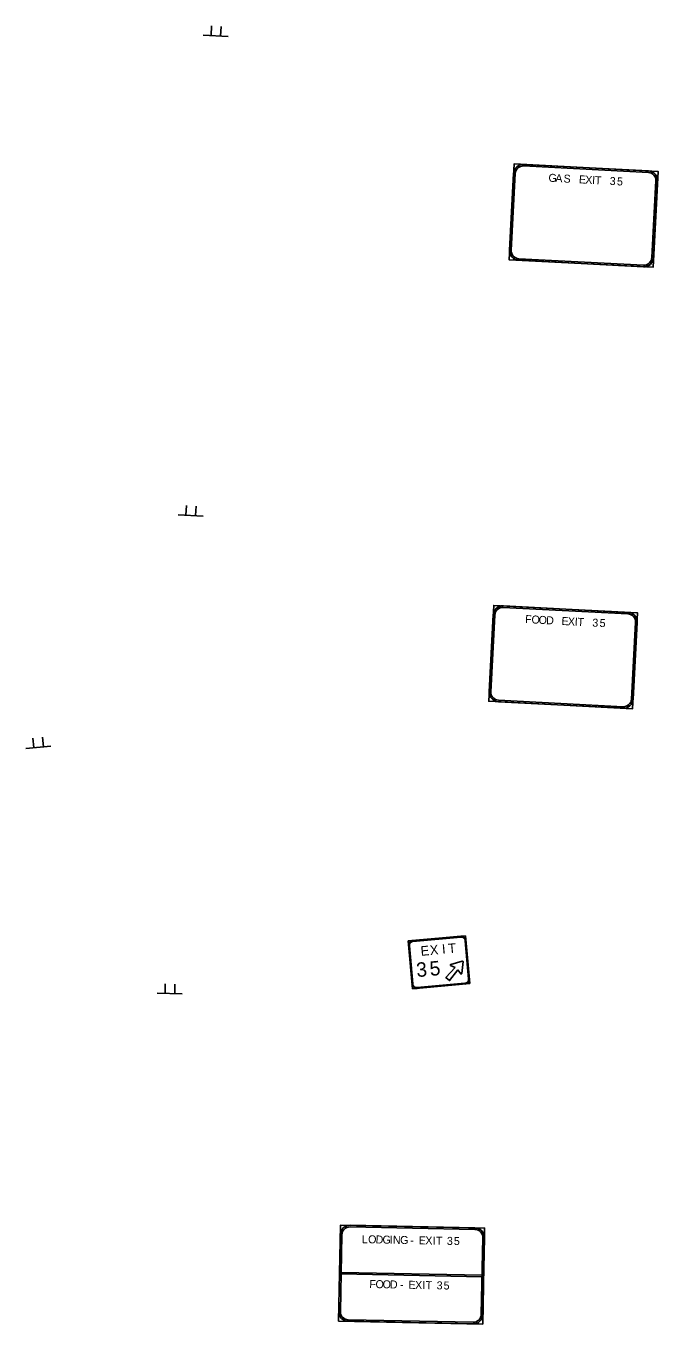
# Model space of a CAD drawing. Extents: x 1581789 to 1622364, y 1043167 to 1103486.
# Drawn here: x 1612565 to 1612828, y 1089298 to 1089839 of the extents above; entities that cross this region are included whole.
import ezdxf

# ---------------------------------------------------------------- set-up
doc = ezdxf.new("R2010")
doc.units = 0
doc.layers.add('RD_PD_PaveDit', color=7, linetype='Continuous')

msp = doc.modelspace()

# ---------------------------------------------------------------- linework, layer by layer
at = {"layer": 'RD_PD_PaveDit'}
for p, q in [((1612649.09, 1089834.18), (1612638.67, 1089834.73)), ((1612641.95, 1089834.56), (1612642.16, 1089838.54)), ((1612645.96, 1089834.35), (1612646.17, 1089838.33)), ((1612638.62, 1089634.46), (1612628.21, 1089635)), ((1612631.49, 1089634.83), (1612631.7, 1089638.82)), ((1612635.5, 1089634.62), (1612635.71, 1089638.61)), ((1612572.17, 1089538.37), (1612571.82, 1089542.34)), ((1612575.29, 1089538.65), (1612564.9, 1089537.71)), ((1612568.17, 1089538.01), (1612567.82, 1089541.99)), ((1612747.92, 1089459.65), (1612724.02, 1089457.51)), ((1612724.02, 1089457.51), (1612725.81, 1089437.59)), ((1612749.71, 1089439.74), (1612747.92, 1089459.65)), ((1612724.74, 1089449.54), (1612724.74, 1089449.54)), ((1612622.81, 1089435.64), (1612622.89, 1089439.63)), ((1612626.82, 1089435.56), (1612626.9, 1089439.55)), ((1612725.81, 1089437.59), (1612749.71, 1089439.74)), ((1612629.95, 1089435.5), (1612619.52, 1089435.71)), ((1612725.81, 1089437.59), (1612725.81, 1089437.59)), ((1612739.75, 1089438.84), (1612739.75, 1089438.84)), ((1612754.79, 1089317.66), (1612696.13, 1089318.84)), ((1612696.14, 1089319.51), (1612754.8, 1089318.32)), ((1612696.14, 1089319.51), (1612696.14, 1089319.51))]:
    msp.add_line(p, q, dxfattribs=at)
for points in [[(1612766.06, 1089741.17), (1612825.98, 1089738.04), (1612828.07, 1089777.98), (1612768.15, 1089781.12), (1612766.06, 1089741.17), (1612766.06, 1089741.17)], [(1612824.04, 1089777.52), (1612772.11, 1089780.24)], [(1612772.15, 1089780.91), (1612824.08, 1089778.19)], [(1612766.27, 1089745.17), (1612767.95, 1089777.13)], [(1612768.61, 1089777.09), (1612766.94, 1089745.13)], [(1612825.52, 1089742.07), (1612827.2, 1089774.02)], [(1612827.86, 1089773.99), (1612826.19, 1089742.03)], [(1612821.99, 1089738.25), (1612770.06, 1089740.97)], [(1612770.09, 1089741.63), (1612822.02, 1089738.91)], [(1612757.58, 1089557.32), (1612817.5, 1089554.18), (1612819.59, 1089594.13), (1612759.67, 1089597.27), (1612757.58, 1089557.32), (1612757.58, 1089557.32)], [(1612815.56, 1089593.67), (1612763.63, 1089596.39)], [(1612763.67, 1089597.06), (1612815.6, 1089594.34)], [(1612757.79, 1089561.32), (1612759.46, 1089593.27)], [(1612760.13, 1089593.24), (1612758.46, 1089561.28)], [(1612817.04, 1089558.21), (1612818.72, 1089590.17)], [(1612819.38, 1089590.13), (1612817.71, 1089558.18)], [(1612813.51, 1089554.39), (1612761.58, 1089557.11)], [(1612761.61, 1089557.78), (1612813.54, 1089555.06)], [(1612726.01, 1089457.69), (1612745.93, 1089459.48)], [(1612745.96, 1089459.14), (1612726.04, 1089457.35)], [(1612749.2, 1089441.7), (1612747.77, 1089457.63)], [(1612724.53, 1089455.54), (1612725.96, 1089439.61)], [(1612741.31, 1089440.99), (1612739.77, 1089442.27), (1612743.54, 1089446.4)], [(1612744.69, 1089445.43), (1612741.31, 1089440.99), (1612741.31, 1089440.99)], [(1612741.71, 1089447.29), (1612743.54, 1089446.4)], [(1612746.56, 1089449.16), (1612741.75, 1089447.75)], [(1612744.69, 1089445.43), (1612745.9, 1089443.79)], [(1612746.35, 1089443.91), (1612746.88, 1089448.89)], [(1612727.77, 1089438.1), (1612747.69, 1089439.89)], [(1612695.07, 1089299.19), (1612755.06, 1089297.98), (1612755.86, 1089337.97), (1612695.87, 1089339.18), (1612695.07, 1089299.19), (1612695.07, 1089299.19)], [(1612751.85, 1089337.39), (1612699.86, 1089338.43)], [(1612699.87, 1089339.1), (1612751.86, 1089338.05)], [(1612696.46, 1089335.17), (1612695.82, 1089303.18)], [(1612754.47, 1089301.99), (1612755.11, 1089333.99)], [(1612755.78, 1089333.97), (1612755.14, 1089301.98)], [(1612751.06, 1089298.06), (1612699.07, 1089299.11)], [(1612699.08, 1089299.78), (1612751.07, 1089298.73)]]:
    msp.add_lwpolyline(points, dxfattribs=at)
for centre, radius, start, end in [((1612771.94, 1089776.92), 4, 87.0018, 177.0014), ((1612771.94, 1089776.92), 3.33, 87.0018, 177.0014), ((1612823.87, 1089774.2), 3.33, 357.0015, 87.0018), ((1612823.87, 1089774.2), 4, 357.0015, 87.0018), ((1612770.27, 1089744.96), 4, 177.0014, 267.0016), ((1612770.27, 1089744.96), 3.33, 177.0014, 267.0016), ((1612822.19, 1089742.24), 4, 267.0016, 357.0018), ((1612822.19, 1089742.24), 3.33, 267.0016, 357.0018), ((1612763.46, 1089593.06), 4, 87.0018, 177.0014), ((1612763.46, 1089593.06), 3.33, 87.0018, 177.0014), ((1612815.39, 1089590.34), 3.33, 357.0015, 87.0018), ((1612815.39, 1089590.34), 4, 357.0015, 87.0018), ((1612761.79, 1089561.11), 4, 177.0014, 267.0016), ((1612761.79, 1089561.11), 3.33, 177.0014, 267.0016), ((1612813.71, 1089558.39), 4, 267.0016, 357.0018), ((1612813.71, 1089558.39), 3.33, 267.0016, 357.0018), ((1612726.19, 1089455.69), 2, 95.1357, 185.1353), ((1612726.19, 1089455.69), 1.67, 95.1357, 185.1353), ((1612746.11, 1089457.48), 2, 5.1354, 95.1357), ((1612746.11, 1089457.48), 1.67, 5.1354, 95.1357), ((1612741.82, 1089447.51), 0.25, 106.3135, 244.0978), ((1612746.63, 1089448.92), 0.25, 353.9573, 106.3132), ((1612727.62, 1089439.76), 2, 185.1353, 275.1355), ((1612727.62, 1089439.76), 1.67, 185.1353, 275.1355), ((1612746.1, 1089443.93), 0.25, 216.1736, 353.9573), ((1612747.54, 1089441.55), 1.67, 275.1355, 5.1357), ((1612747.54, 1089441.55), 2, 275.1355, 5.1357), ((1612699.79, 1089335.1), 4, 88.8471, 178.8467), ((1612699.79, 1089335.1), 3.33, 88.8471, 178.8467), ((1612751.78, 1089334.06), 3.33, 358.8469, 88.8471), ((1612751.78, 1089334.06), 4, 358.8469, 88.8471), ((1612699.15, 1089303.11), 4, 178.8467, 268.8469), ((1612699.15, 1089303.11), 3.33, 178.8467, 268.8469), ((1612751.14, 1089302.06), 4, 268.8469, 358.8472), ((1612751.14, 1089302.06), 3.33, 268.8469, 358.8472)]:
    msp.add_arc(centre, radius, start, end, dxfattribs=at)

# ---------------------------------------------------------------- texts
for s, height, rotation, p in [('G', 3.33, 357.0015, (1612782.38, 1089773.7)), ('A', 3.33, 357.0015, (1612785.24, 1089773.55)), ('S', 3.33, 357.0015, (1612788.65, 1089773.37)), ('E', 3.33, 357.0015, (1612795.05, 1089773.04)), ('X', 3.33, 357.0015, (1612797.7, 1089772.9)), ('I', 3.33, 357.0015, (1612800.56, 1089772.75)), ('T', 3.33, 357.0015, (1612801.7, 1089772.69)), ('3', 3.33, 357.0015, (1612807.89, 1089772.36)), ('5', 3.33, 357.0015, (1612810.91, 1089772.2)), ('F', 3.33, 357.0015, (1612772.67, 1089589.91)), ('O', 3.33, 357.0015, (1612775.32, 1089589.77)), ('O', 3.33, 357.0015, (1612778.28, 1089589.62)), ('D', 3.33, 357.0015, (1612781.4, 1089589.45)), ('E', 3.33, 357.0015, (1612787.8, 1089589.12)), ('X', 3.33, 357.0015, (1612790.45, 1089588.98)), ('I', 3.33, 357.0015, (1612793.32, 1089588.83)), ('T', 3.33, 357.0015, (1612794.46, 1089588.77)), ('3', 3.33, 357.0015, (1612800.65, 1089588.44)), ('5', 3.33, 357.0015, (1612803.67, 1089588.29)), ('X', 4, 5.1354, (1612733.23, 1089451.64)), ('I', 4, 5.1354, (1612738.29, 1089452.1)), ('T', 4, 5.1354, (1612740.86, 1089452.33)), ('E', 4, 5.1354, (1612729.38, 1089451.29)), ('3', 6, 5.1354, (1612727.68, 1089442.44)), ('5', 6, 5.1354, (1612733.23, 1089442.94)), ('L', 3.33, 358.8469, (1612704.68, 1089331.67)), ('O', 3.33, 358.8469, (1612707.33, 1089331.62)), ('D', 3.33, 358.8469, (1612710.46, 1089331.55)), ('G', 3.33, 358.8469, (1612713.32, 1089331.5)), ('I', 3.33, 358.8469, (1612716.34, 1089331.43)), ('N', 3.33, 358.8469, (1612717.64, 1089331.41)), ('G', 3.33, 358.8469, (1612720.66, 1089331.35)), ('-', 3.33, 358.8469, (1612724.89, 1089331.26)), ('E', 3.33, 358.8469, (1612728.42, 1089331.19)), ('X', 3.33, 358.8469, (1612731.15, 1089331.14)), ('I', 3.33, 358.8469, (1612734.18, 1089331.08)), ('T', 3.33, 358.8469, (1612735.58, 1089331.05)), ('3', 3.33, 358.8469, (1612740.13, 1089330.96)), ('5', 3.33, 358.8469, (1612743.03, 1089330.9)), ('F', 3.33, 358.8469, (1612707.83, 1089313)), ('O', 3.33, 358.8469, (1612710.41, 1089312.95)), ('O', 3.33, 358.8469, (1612713.37, 1089312.89)), ('D', 3.33, 358.8469, (1612716.39, 1089312.83)), ('E', 3.33, 358.8469, (1612724.15, 1089312.68)), ('X', 3.33, 358.8469, (1612726.88, 1089312.62)), ('I', 3.33, 358.8469, (1612729.9, 1089312.56)), ('T', 3.33, 358.8469, (1612731.3, 1089312.53)), ('3', 3.33, 358.8469, (1612735.85, 1089312.44)), ('5', 3.33, 358.8469, (1612738.76, 1089312.38)), ('-', 3.33, 358.8469, (1612720.62, 1089312.75))]:
    msp.add_text(s, height=height, rotation=rotation, dxfattribs=at).set_placement(p)

doc.saveas('drawing.dxf')
